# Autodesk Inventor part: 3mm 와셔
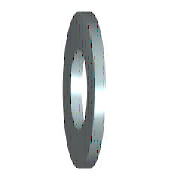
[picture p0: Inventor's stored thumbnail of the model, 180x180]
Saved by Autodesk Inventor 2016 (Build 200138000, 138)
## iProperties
Created: 2012-02
Part Number: 3mm 와셔
Material: 스테인리스강
Description: 평면 와셔 - 대형 시리즈 - 제품 등급 A
Document SubType Name: Modeling
Standard: ISO 7093 A
Designer: mduedu
Standard Revision: First Edition 2000-06-01
Standards Organization: ISO
Language: ko-KR
Size Designation: ST 3 - 140 HV - A
Categories: <MemberInstance><Categories><Category DisplayName="조임쇠" InternalName="e4da775c-781d-43d5-af7c-5136215cf5a6" Mnemonic="FSTN"><Category DisplayName="와셔" InternalN
Density: 8.08 g/cm^3
Appearance: 파란색 - 벽 페인트 - 광택
Mass: 0.359235 g
Surface Area: 1.41811 cm^2
Volume: 0.0444598 cm^3
IsCustomPart: 1
Author: mduedu
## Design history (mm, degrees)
sketch "스케치"
  geometry: C1 r 4.5 at (0, 0); C2 r 1.6 at (0, 0); 1 further point
  constraints: 2 centre point, 2 coincident
  dimensions: "d0" = 3.2 diameter of C2 (= SD1); "d1" = 9 diameter of C1 (= SD2)
extrude "본체" new body sketch "스케치" distance "d2" = 0.8 (= SD); taper "d3" = 0 deg
workaxis "Work Axis1"
workplane "Work Plane1"
sketch "스케치5"
  geometry: 2 further points
  constraints: 1 coincident
body "Solid1"
other parameters: "SD1" = 3.2 [user parameter; used in 1 equation term], "SD2" = 9 [user parameter; used in 1 equation term], "SD" = 0.8 [user parameter; used in 1 equation term], "d4" = 0, "d5" = 0, "d6" = 0, "d7" = 0, "NND" = 3 [user parameter]
